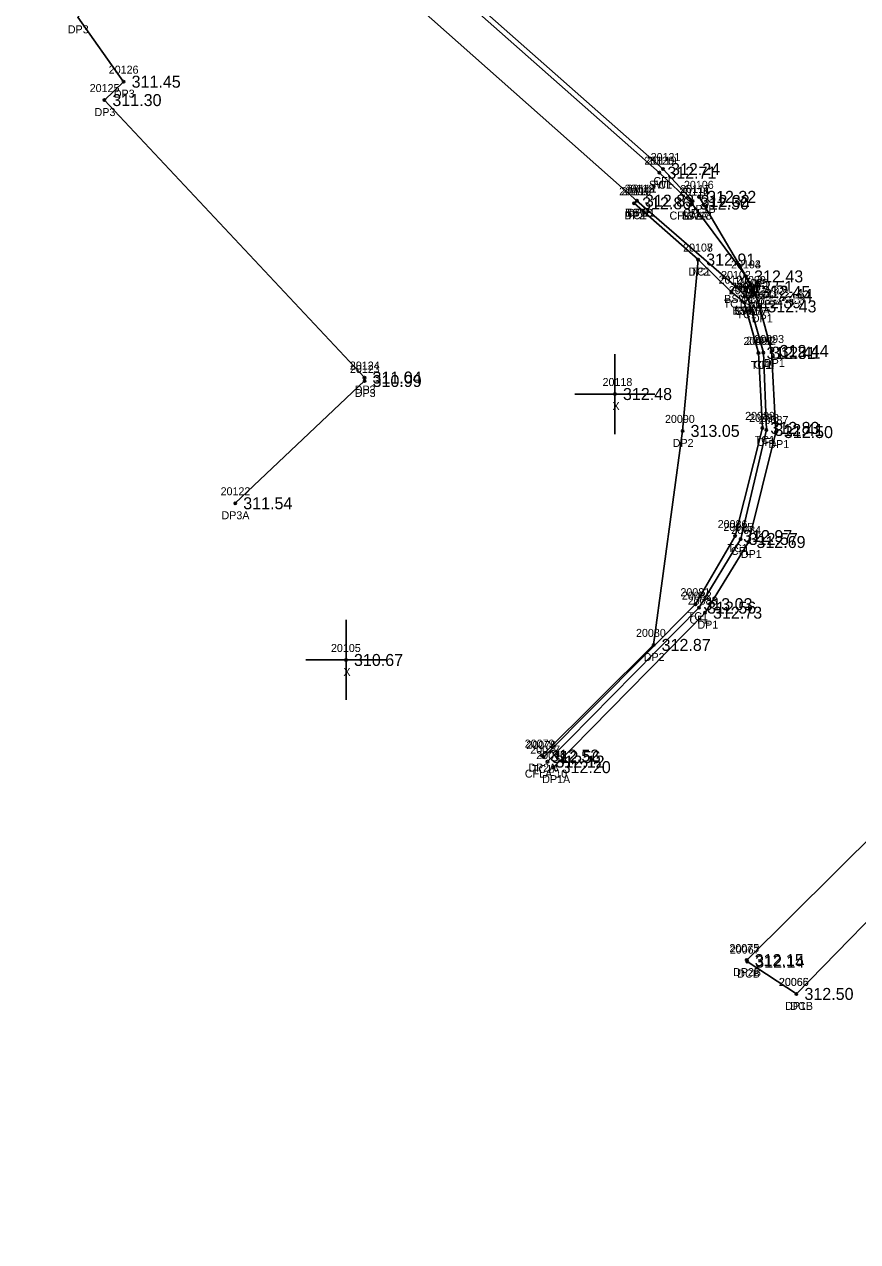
# Model space of a CAD drawing. Extents: x 1970242 to 1971082, y 803104 to 803947.
# Drawn here: x 1970789.1 to 1970893.2, y 803139.6 to 803291.7 of the extents above; entities that cross this region are included whole.
import ezdxf

# ---------------------------------------------------------------- set-up
doc = ezdxf.new("R2010")
doc.units = 0
for name, color, linetype in [('RD_DTM_BkLn2', 7, 'Continuous'), ('RD_EX_Conc', 7, 'Continuous'), ('RD_EX_Conc_txCode', 7, 'Continuous'), ('RD_EX_Driveway', 7, 'Continuous'), ('RD_EX_Driveway_txCode', 7, 'Continuous'), ('RD_EX_Misc', 7, 'Continuous'), ('RD_EX_Misc_txCode', 7, 'Continuous'), ('RD_EX_TX_Conc_ELEV', 7, 'Continuous'), ('RD_EX_TX_Driveway_ELEV', 7, 'Continuous'), ('RD_EX_TX_Misc_ELEV', 7, 'Continuous'), ('RD_SMD_Locator', 7, 'Continuous')]:
    doc.layers.add(name, color=color, linetype=linetype)

msp = doc.modelspace()

# ---------------------------------------------------------------- linework, layer by layer
at = {"layer": 'RD_DTM_BkLn2'}
for points in [[(1970872.53, 803269.28), (1970868.47, 803273.14), (1970819.57, 803316.35), (1970792.83, 803340.24), (1970791.56, 803341.26)], [(1970854, 803200.12), (1970872.97, 803219.22), (1970877.94, 803227.73), (1970881.34, 803241.25), (1970880.86, 803250.61), (1970879.06, 803256.95), (1970877.46, 803258.27), (1970873.32, 803262.28), (1970865.32, 803269.32), (1970865.67, 803269.64)]]:
    msp.add_lwpolyline(points, dxfattribs=at)
at = {"layer": 'RD_EX_Conc'}
for points in [[(1970879.58, 803257.38), (1970880.21, 803258.23), (1970879.31, 803260.18), (1970872.53, 803269.28), (1970868.47, 803273.14), (1970819.57, 803316.35), (1970792.83, 803340.24), (1970791.56, 803341.26)], [(1970872.53, 803269.28), (1970872.62, 803269.6), (1970868.93, 803273.59), (1970819.97, 803316.84), (1970793.14, 803340.78), (1970791.95, 803341.72)], [(1970879.58, 803257.38), (1970878.06, 803258.86), (1970865.67, 803269.64), (1970816.24, 803313.45), (1970789.11, 803337.91)], [(1970854.49, 803199.55), (1970873.43, 803218.79), (1970878.63, 803227.37), (1970881.85, 803240.99), (1970881.47, 803250.65), (1970879.58, 803257.38)], [(1970895.99, 803191.21), (1970896.36, 803190.58), (1970896.84, 803190.29), (1970900.63, 803185.94), (1970885.6, 803170.52), (1970879.45, 803174.56)]]:
    msp.add_lwpolyline(points, dxfattribs=at)
at = {"layer": 'RD_EX_Driveway'}
for points in [[(1970815.47, 803231.83), (1970831.63, 803247.11), (1970831.62, 803247.54), (1970799.12, 803282.21), (1970801.52, 803284.51), (1970795.78, 803292.55), (1970816.24, 803313.45)], [(1970853.81, 803200.3), (1970867.75, 803214.13), (1970871.37, 803240.87), (1970873.32, 803262.28), (1970865.32, 803269.32), (1970865.67, 803269.64), (1970816.24, 803313.45)], [(1970855.26, 803198.86), (1970874.18, 803218.16), (1970879.6, 803226.99), (1970883.03, 803240.73), (1970882.49, 803250.86), (1970880.97, 803256.43), (1970880.48, 803257.86), (1970879.31, 803260.18), (1970873.44, 803270.12)], [(1970952.37, 803201.57), (1970942.58, 803206.17), (1970938.12, 803207.42), (1970925.47, 803208.94), (1970910.17, 803203.91), (1970902.62, 803198.01), (1970895.99, 803191.21), (1970879.38, 803174.75)], [(1970971.84, 803139.57), (1970941.59, 803165.98), (1970933.19, 803161.96), (1970929.41, 803160.69), (1970902.05, 803185.25), (1970901.29, 803185.97), (1970900.63, 803185.94), (1970885.6, 803170.52)]]:
    msp.add_lwpolyline(points, dxfattribs=at)
at = {"layer": 'RD_EX_Misc'}
for p, q in [((1970862.92, 803240.48), (1970862.92, 803250.48)), ((1970857.92, 803245.48), (1970867.92, 803245.48)), ((1970829.31, 803207.25), (1970829.31, 803217.25)), ((1970824.31, 803212.25), (1970834.31, 803212.25))]:
    msp.add_line(p, q, dxfattribs=at)
at = {"layer": 'RD_SMD_Locator'}
for centre in [(1970801.52, 803284.51), (1970799.12, 803282.21), (1970868.47, 803273.14), (1970868.47, 803273.14), (1970868.93, 803273.59), (1970865.67, 803269.64), (1970865.67, 803269.64), (1970865.67, 803269.64), (1970872.62, 803269.6), (1970873.44, 803270.12), (1970865.32, 803269.32), (1970865.32, 803269.32), (1970872.53, 803269.28), (1970872.53, 803269.28), (1970872.53, 803269.28), (1970873.32, 803262.28), (1970873.32, 803262.28), (1970878.06, 803258.86), (1970879.31, 803260.18), (1970879.31, 803260.18), (1970877.46, 803258.27), (1970879.58, 803257.38), (1970879.58, 803257.38), (1970879.58, 803257.38), (1970880.21, 803258.23), (1970880.48, 803257.86), (1970879.06, 803256.95), (1970880.97, 803256.43), (1970880.86, 803250.61), (1970881.47, 803250.65), (1970882.49, 803250.86), (1970831.62, 803247.54), (1970831.63, 803247.11), (1970862.92, 803245.48), (1970871.37, 803240.87), (1970881.34, 803241.25), (1970881.85, 803240.99), (1970883.03, 803240.73), (1970815.47, 803231.83), (1970877.94, 803227.73), (1970878.63, 803227.37), (1970879.6, 803226.99), (1970872.97, 803219.22), (1970873.43, 803218.79), (1970874.18, 803218.16), (1970867.75, 803214.13), (1970829.31, 803212.25), (1970853.81, 803200.3), (1970854, 803200.12), (1970854.49, 803199.55), (1970855.26, 803198.86), (1970879.38, 803174.75), (1970879.45, 803174.56), (1970885.6, 803170.52), (1970885.6, 803170.52)]:
    msp.add_circle(centre, 0.15, dxfattribs=at)

# ---------------------------------------------------------------- texts
at = {"layer": 'RD_EX_Conc_txCode'}
for s, p in [('20120', (1970866.59, 803274.14)), ('20119', (1970866.91, 803274.14)), ('20121', (1970867.38, 803274.59)), ('20109', (1970863.45, 803270.32)), ('20112', (1970864.12, 803270.64)), ('20111', (1970864.4, 803270.64)), ('SWL', (1970867.17, 803271.14)), ('TC1', (1970867.51, 803271.14)), ('CFL', (1970867.72, 803271.59)), ('20116', (1970870.96, 803270.28)), ('20114', (1970870.98, 803270.28)), ('20115', (1970870.98, 803270.28)), ('20117', (1970871.07, 803270.6)), ('TC1B', (1970864.24, 803267.64)), ('BSW1', (1970864.19, 803267.64)), ('TC1', (1970864.36, 803267.32)), ('CFLA 18', (1970869.74, 803267.28)), ('TC1A', (1970871.08, 803267.28)), ('SWL', (1970871.24, 803267.28)), ('CFL', (1970871.42, 803267.6)), ('20107', (1970871.44, 803263.28)), ('20103', (1970877.43, 803261.18)), ('TC1', (1970872.36, 803260.28)), ('20102', (1970876.18, 803259.86)), ('20101', (1970875.87, 803259.27)), ('20096', (1970877.39, 803258.38)), ('20097', (1970877.42, 803258.38)), ('20098', (1970877.42, 803258.38)), ('SWL', (1970878.02, 803258.18)), ('20099', (1970878.06, 803259.23)), ('BSW1', (1970876.58, 803256.86)), ('20100', (1970877.15, 803257.95)), ('TC1', (1970876.5, 803256.27)), ('BSW1A', (1970877.61, 803255.38)), ('SWLA', (1970877.8, 803255.38)), ('CFLB', (1970877.9, 803255.38)), ('TC1', (1970878.1, 803254.95)), ('SWL', (1970878.92, 803256.23)), ('20091', (1970878.98, 803251.61)), ('20092', (1970879.32, 803251.65)), ('TC1', (1970879.9, 803248.61)), ('CFL', (1970880.27, 803248.65)), ('20089', (1970879.19, 803242.25)), ('20088', (1970879.69, 803241.99)), ('TC1', (1970880.38, 803239.25)), ('CFL', (1970880.65, 803238.99)), ('20086', (1970875.76, 803228.73)), ('20085', (1970876.47, 803228.37)), ('TC1', (1970876.98, 803225.73)), ('CFL', (1970877.42, 803225.37)), ('20081', (1970871.1, 803220.22)), ('20082', (1970871.28, 803219.79)), ('TC1', (1970872.01, 803217.22)), ('CFL', (1970872.23, 803216.79)), ('20078', (1970851.84, 803201.12)), ('20077', (1970852.34, 803200.55)), ('CFLA 10', (1970851.66, 803197.55)), ('TC1A', (1970852.55, 803198.12)), ('20067', (1970877.27, 803175.56)), ('DCB', (1970878.2, 803172.56)), ('20066', (1970883.4, 803171.52)), ('DC', (1970884.82, 803168.52))]:
    msp.add_text(s, height=1, dxfattribs=at).set_placement(p)
at = {"layer": 'RD_EX_Driveway_txCode'}
for s, p in [('DP3', (1970794.55, 803290.55)), ('20126', (1970799.66, 803285.51)), ('20125', (1970797.28, 803283.21)), ('DP3', (1970800.29, 803282.51)), ('DP3', (1970797.89, 803280.21)), ('20110', (1970863.73, 803270.32)), ('20113', (1970864.12, 803270.64)), ('20106', (1970871.54, 803271.12)), ('DP2', (1970864.09, 803267.32)), ('DP2', (1970864.44, 803267.64)), ('DP1B', (1970872.02, 803268.12)), ('20108', (1970871.44, 803263.28)), ('20104', (1970877.43, 803261.18)), ('DP2', (1970872.09, 803260.28)), ('20095', (1970878.32, 803258.86)), ('DP1', (1970878.36, 803258.18)), ('20094', (1970878.81, 803257.43)), ('DP1', (1970879.53, 803255.86)), ('DP1', (1970880.03, 803254.43)), ('20093', (1970880.33, 803251.86)), ('20124', (1970829.79, 803248.54)), ('20123', (1970829.8, 803248.11)), ('DP1', (1970881.54, 803248.86)), ('DP3', (1970830.4, 803245.54)), ('DP3', (1970830.41, 803245.11)), ('20090', (1970869.17, 803241.87)), ('20087', (1970880.88, 803241.73)), ('DP2', (1970870.14, 803238.87)), ('DP1', (1970882.09, 803238.73)), ('20122', (1970813.64, 803232.83)), ('DP3A', (1970813.75, 803229.83)), ('20084', (1970877.45, 803227.99)), ('DP1', (1970878.66, 803224.99)), ('20083', (1970872.02, 803219.16)), ('DP1', (1970873.23, 803216.16)), ('20080', (1970865.55, 803215.13)), ('DP2', (1970866.52, 803212.13)), ('20079', (1970851.65, 803201.3)), ('20076', (1970853.08, 803199.86)), ('DP2A', (1970852.09, 803198.3)), ('DP1A', (1970853.83, 803196.86)), ('20075', (1970877.22, 803175.75)), ('DP2B', (1970877.68, 803172.75)), ('20065', (1970883.42, 803171.52)), ('DP1B', (1970884.18, 803168.52))]:
    msp.add_text(s, height=1, dxfattribs=at).set_placement(p)
at = {"layer": 'RD_EX_Misc_txCode'}
for s, p in [('20118', (1970861.37, 803246.48)), ('X', (1970862.61, 803243.48)), ('20105', (1970827.43, 803213.25)), ('X', (1970828.99, 803210.25))]:
    msp.add_text(s, height=1, dxfattribs=at).set_placement(p)
at = {"layer": 'RD_EX_TX_Conc_ELEV'}
for s, p in [('312.24', (1970869.93, 803272.84)), ('312.71', (1970869.47, 803272.39)), ('312.71', (1970869.47, 803272.39)), ('312.86', (1970866.32, 803268.57)), ('312.83', (1970866.67, 803268.89)), ('312.83', (1970866.67, 803268.89)), ('312.50', (1970873.53, 803268.53)), ('312.50', (1970873.53, 803268.53)), ('312.50', (1970873.53, 803268.53)), ('312.32', (1970873.62, 803268.85)), ('312.91', (1970874.32, 803261.53)), ('312.43', (1970880.31, 803259.43)), ('312.92', (1970878.46, 803257.52)), ('312.51', (1970879.06, 803258.11)), ('312.45', (1970881.21, 803257.48)), ('312.89', (1970880.06, 803256.2)), ('312.49', (1970880.58, 803256.63)), ('312.49', (1970880.58, 803256.63)), ('312.49', (1970880.58, 803256.63)), ('312.41', (1970882.47, 803249.9)), ('312.81', (1970881.86, 803249.86)), ('312.83', (1970882.34, 803240.5)), ('312.41', (1970882.85, 803240.24)), ('312.97', (1970878.94, 803226.98)), ('312.57', (1970879.63, 803226.62)), ('313.03', (1970873.97, 803218.47)), ('312.56', (1970874.43, 803218.04)), ('312.56', (1970855, 803199.37)), ('312.12', (1970855.49, 803198.8)), ('312.14', (1970880.45, 803173.81)), ('312.50', (1970886.6, 803169.77))]:
    msp.add_text(s, height=1.5, dxfattribs=at).set_placement(p)
at = {"layer": 'RD_EX_TX_Driveway_ELEV'}
for s, p in [('311.45', (1970802.52, 803283.76)), ('311.30', (1970800.12, 803281.46)), ('312.86', (1970866.32, 803268.57)), ('312.83', (1970866.67, 803268.89)), ('312.32', (1970874.44, 803269.37)), ('312.91', (1970874.32, 803261.53)), ('312.43', (1970880.31, 803259.43)), ('312.44', (1970881.48, 803257.11)), ('312.43', (1970881.97, 803255.68)), ('312.44', (1970883.49, 803250.11)), ('311.04', (1970832.62, 803246.79)), ('310.99', (1970832.63, 803246.36)), ('313.05', (1970872.37, 803240.12)), ('312.50', (1970884.03, 803239.98)), ('311.54', (1970816.47, 803231.08)), ('312.69', (1970880.6, 803226.24)), ('312.73', (1970875.18, 803217.41)), ('312.87', (1970868.75, 803213.38)), ('312.52', (1970854.81, 803199.55)), ('312.20', (1970856.26, 803198.11)), ('312.15', (1970880.38, 803174)), ('312.50', (1970886.6, 803169.77))]:
    msp.add_text(s, height=1.5, dxfattribs=at).set_placement(p)
at = {"layer": 'RD_EX_TX_Misc_ELEV'}
for s, p in [('312.48', (1970863.92, 803244.73)), ('310.67', (1970830.31, 803211.5))]:
    msp.add_text(s, height=1.5, dxfattribs=at).set_placement(p)

doc.saveas('drawing.dxf')
